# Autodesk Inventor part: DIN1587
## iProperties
Shininess: 25.0
Length Units: 11269
Angle Units: 11279
Time Units: 11290
Mass Units: 11283
Length Display Precision: 3
Angle Display Precision: 2
Compacted: True
Created: 2001-01
Part Number: DIN1587
Material: 6
Description: Hex Domed Cap Nut M8
Vendor: DIN1587
Document SubType Name: Modeling
Designer: Robbert Osinga
Density: 0.0
Volumn: 0.0
Area: 0.0
PropertySet Name: Model Information
Control State: 0
Master: False
Checked Out: False
Checked Out By: ?
Author: Robbert Osinga
Revision Number: 0
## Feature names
1. Hole2
2. Revolution1
3. Mirror1
4. Revolution2
5. Extrusion1
